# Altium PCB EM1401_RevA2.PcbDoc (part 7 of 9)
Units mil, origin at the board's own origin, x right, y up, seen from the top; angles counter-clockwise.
Board outline 7800 x 5300 mil, 6 copper layers (Top Layer, MidLayer1, MidLayer2, MidLayer3, MidLayer4, Bottom Layer), stack 16.8 mil thick; 751 components, 531 nets, 2554 pads, 1388 vias.
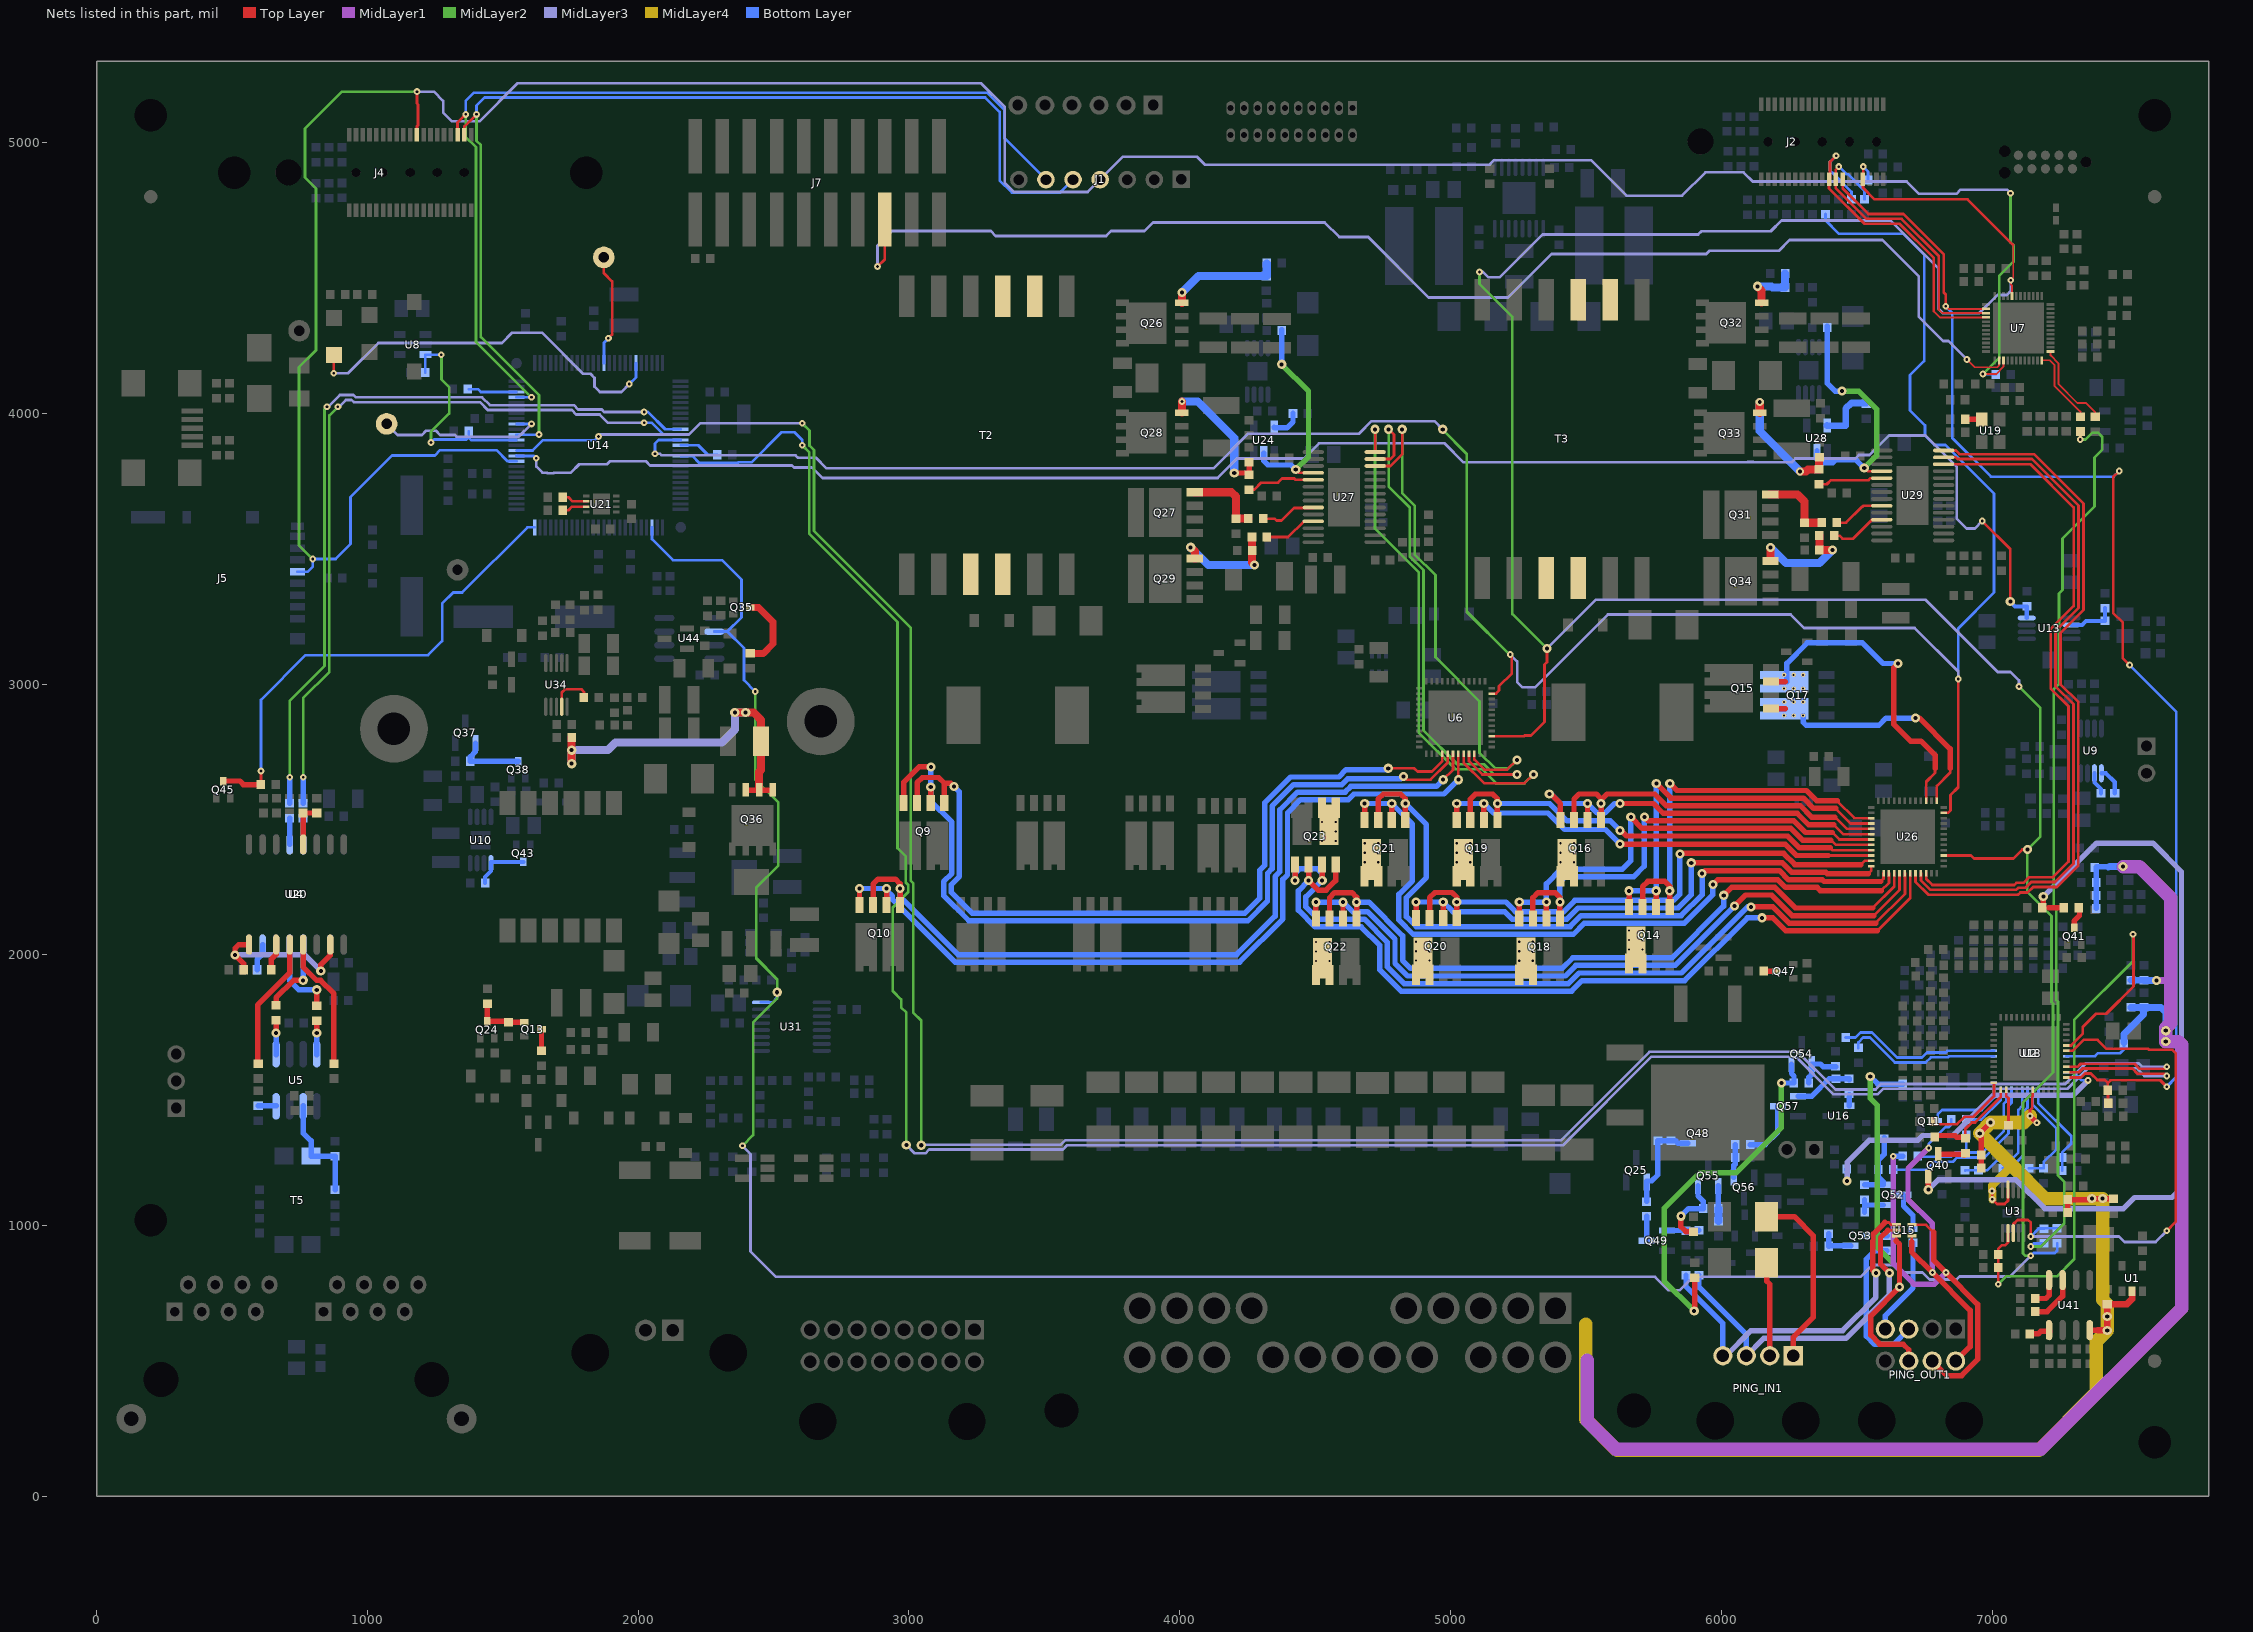
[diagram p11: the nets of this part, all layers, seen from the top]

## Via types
v1: diameter 25, hole 10, Top Layer to Bottom Layer, tented both sides, 275 vias
v2: diameter 16, hole 8, Top Layer to Bottom Layer, tented both sides, 240 vias
v3: diameter 34, hole 15, Top Layer to Bottom Layer, tented both sides, 158 vias
v4: diameter 34, hole 15, Top Layer to Bottom Layer, 154 vias
v5: diameter 34, hole 15, Top Layer to Bottom Layer, tented top, 95 vias
v6: diameter 34, hole 15, Top Layer to Bottom Layer, tented bottom, 89 vias
v7: diameter 25, hole 10, Top Layer to Bottom Layer, tented bottom, 75 vias
v8: diameter 25, hole 10, Top Layer to Bottom Layer, 62 vias
v9: diameter 28, hole 8, Top Layer to Bottom Layer, tented both sides, 60 vias
v10: diameter 24, hole 8, Top Layer to Bottom Layer, 53 vias
v11: diameter 25, hole 10, Top Layer to Bottom Layer, tented top, 28 vias
v12: diameter 50, hole 28, Top Layer to Bottom Layer, 28 vias
v13: diameter 25, hole 8, Top Layer to Bottom Layer, tented both sides, 18 vias
v14: diameter 50, hole 28, Top Layer to Bottom Layer, tented top, 12 vias
v15: diameter 25, hole 8, Top Layer to Bottom Layer, tented top, 9 vias
v16: diameter 20, hole 8, Top Layer to Bottom Layer, tented both sides, 9 vias
v17: diameter 24, hole 8, Top Layer to Bottom Layer, tented bottom, 4 vias
v18: diameter 24, hole 8, Top Layer to Bottom Layer, tented top, 4 vias
v19: diameter 28, hole 10, Top Layer to Bottom Layer, tented both sides, 3 vias
v20: diameter 35, hole 14, Top Layer to Bottom Layer, 3 vias
v21: diameter 50, hole 28, Top Layer to Bottom Layer, tented both sides, 2 vias
v22: diameter 50, hole 28, Top Layer to Bottom Layer, tented bottom, 2 vias
v23: diameter 30, hole 14, Top Layer to Bottom Layer, tented top, 2 vias
v24: diameter 28, hole 10, Top Layer to Bottom Layer, 1 vias
v25: diameter 35, hole 14, Top Layer to Bottom Layer, tented both sides, 1 vias
v26: diameter 35, hole 14, Top Layer to Bottom Layer, tented top, 1 vias

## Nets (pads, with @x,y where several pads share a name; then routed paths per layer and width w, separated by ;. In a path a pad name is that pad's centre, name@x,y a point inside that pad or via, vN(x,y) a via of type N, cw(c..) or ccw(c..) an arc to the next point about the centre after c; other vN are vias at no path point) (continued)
NetQ9_1: Q9.1 Q9.3 U6.16 | length 3029.8
  Top Layer w10: v4(4770,2689) 4866,2689 4878,2677 4931.29,2677 4969.7,2715.41 U6.16@4969.7,2742.39
  Top Layer w20: Q9.3@3030.42,2560 3030.42,2636 3049.42,2655 3109.42,2655 3130.42,2634 ; Q9.1@3130.42,2560 3130.42,2634 ; v4(3166.42,2622) 3154.42,2634 3130.42,2634
  Bottom Layer w20: v4(3166.42,2622) 3186.42,2602 3186.42,2289.5 3156.42,2259.5 3156.42,2230.5 3232.92,2154 4240.2,2154 4296,2209.8 4296,2312.63 4313.42,2330.05 4313.42,2561.22 4409.2,2657 4587.6,2657 4614.6,2684 4765,2684 v4(4770,2689)
NetQ9_2: Q9.2 Q9.4 U6.17 | length 3161.4
  Top Layer w10: v4(4826,2659) 4838,2647 4926.75,2647 4989.39,2709.64 U6.17@4989.39,2742.39
  Top Layer w20: Q9.4@2980.42,2560 2980.42,2637 3037.42,2694 v4(3081.42,2694) ; Q9.2@3080.42,2560 v4(3080.42,2620)
  Bottom Layer w20: v4(3081.42,2694) 3080.42,2693 v4(3080.42,2620) 3080.42,2568 3158.42,2490 3158.42,2301.1 3128.42,2271.1 3128.42,2218.9 3221.32,2126 4251.79,2126 4324,2198.21 4324,2301.03 4341.42,2318.45 4341.42,2549.62 4420.79,2629 4599.2,2629 4620.2,2650 4817,2650 v4(4826,2659)
NetQ10_1: Q10.1 Q10.3 U6.18 | length 2990.1
  Top Layer w10: v4(4973,2647) 5009.07,2683.07 U6.18@5009.07,2742.39
  Top Layer w20: Q10.3@2867.42,2185 2867.42,2261 2886.42,2280 2950,2280 2967.42,2262.58 v4(2967.42,2245) Q10.1@2967.42,2185
  Bottom Layer w20: v4(2967.42,2245) 2967.42,2215.57 3181.99,2001 4210,2001 4352,2143 4352,2289.43 4370,2307.43 4370,2536 4435,2601 4610.79,2601 4631.79,2622 4948,2622 v4(4973,2647)
NetQ10_2: Q10.2 Q10.4 U6.19 | length 3049.6
  Top Layer w10: v4@5028.76,2647 U6.19@5028.76,2742.39
  Top Layer w20: Q10.4@2817.42,2185 v4(2817.42,2245) ; Q10.2@2917.42,2185 v4(2917.42,2245)
  Bottom Layer w20: v4(2817.42,2245) v4(2917.42,2245) 2917.42,2238.58 2939.42,2216.58 2939.42,2203.97 3170.39,1973 4221.6,1973 4381,2132.4 4381,2278.84 4398,2295.84 4398,2524.4 4446.6,2573 4622.39,2573 4643.39,2594 4976,2594 v4(5029,2647)
NetQ11_3: Q11.3 U18.1 | length 313.3
  Bottom Layer w10: Q11.3@6799,1386 6799,1411 6815.5,1427.5 6961.5,1427.5 7006.84,1472.84 U18.1@7006.84,1527.66
NetQ13_1: Q13.1 Q24.3 R210.1 R211.1 | length 199.7
  Top Layer w20: R210.1@1443,1815 Q24.3@1443,1755 1520.01,1755 1521,1755.99 1526.4,1750.59 Q13.1@1580.01,1750.59
NetQ13_3: Q13.3 R176.1 | length 78.9
  Top Layer w20: R176.1@1643,1646.12 Q13.3@1643,1725
NetQ14_1: Q14.1 Q14.3 U26.3 | length 1462.4
  Top Layer w10: 6428,2569 6492.1,2504.9 U26.3@6554.06,2504.9
  Top Layer w20: Q14.3@5709.5,2176.58 5709.5,2252.58 5728.5,2271.58 5792.08,2271.58 5809.5,2254.17 v4(5809.5,2236.58) Q14.1@5809.5,2176.58 ; v4(5810,2633) 5836,2607 6314.77,2607 6352.77,2569 6428,2569
  Bottom Layer w20: v4(5809.5,2236.58) 5809.5,2632.5 v4(5810,2633)
NetQ14_2: Q14.2 Q14.4 U26.4 | length 1471.9
  Top Layer w10: 6422,2541 6477.79,2485.21 U26.4@6554.06,2485.21
  Top Layer w20: Q14.4@5659.5,2176.58 v4(5659.5,2236.58) ; Q14.2@5759.5,2176.58 v4(5759.5,2236.58) ; v4(5760,2633) 5814,2579 6303.17,2579 6341.17,2541 6422,2541
  Bottom Layer w20: v4(5659.5,2236.58) v4(5759.5,2236.58) 5759.5,2632.5 v4(5760,2633)
NetQ14_5: Q14.5 Q14.6 Q15.1 Q17.5 Q17.6 Q18.5 Q18.6 Q20.5 Q20.6 Q22.5 Q22.6 U26.37 | length 894
  Top Layer w10: U26.37@6796.18,2569.86 6796.18,2623.31 6845.42,2672.54 6845.42,2689
  Top Layer w20: Q15.1@6184.27,2909.24 6235.94,2909.24 ; v4(6716.79,2874.62) 6731.79,2874.62 6845.42,2761 6845.42,2689
  Bottom Layer w20: v2(6302.09,2884) 6302.09,2859.33 6313.42,2848 6581.54,2848 6608.17,2874.62 v4(6716.79,2874.62)
  other v2: 4503,1977.99 4553,1977.99 5254,1978.34 5304,1978.34 4873,1978.67 4923,1978.67 4503,2012.99 4553,2012.99 5254,2013.34 5304,2013.34 4873,2013.67 4923,2013.67 5659.5,2019.92 5709.5,2019.92 4503,2047.99 4553,2047.99 5254,2048.34 5304,2048.34 4873,2048.67 4923,2048.67 5659.5,2054.92 5709.5,2054.92 5659.5,2089.92 5709.5,2089.92 6232.09,2884 6267.09,2884 6232.09,2934 6267.09,2934 6302.09,2934
NetQ15_3: Q15.3 Q16.5 Q16.6 Q17.7 Q17.8 Q19.5 Q19.6 Q21.5 Q21.6 Q23.5 Q23.6 U26.39 | length 1203.8
  Top Layer w10: U26.39@6756.81,2569.86 6756.81,2639.4 6789.42,2672 6789.42,2689
  Top Layer w20: Q15.3@6184.27,3009.24 6235.94,3009.24 ; v6(6652.42,3076) 6637.42,3061 6637.42,2851 6698.92,2789.5 6737.51,2789.5 6789.42,2737.6 6789.42,2689
  Bottom Layer w20: Q17.8@6242.09,3009 6242.09,3076.68 6317.42,3152 6521.42,3152 6597.42,3076 v6(6652.42,3076)
  other v2: 4683,2342.34 4733,2342.34 5023,2342.34 5073,2342.34 5406,2342.34 5456,2342.34 4683,2377.34 4733,2377.34 5023,2377.34 5073,2377.34 5406,2377.34 5456,2377.34 4683,2412.34 4733,2412.34 5023,2412.34 5073,2412.34 5406,2412.34 5456,2412.34 4526,2421 4576,2421 4526,2456 4576,2456 4526,2491 4576,2491 6232.09,2984 6267.09,2984 6302.09,2984 6232.09,3034 6267.09,3034 6302.09,3034
NetQ16_1: Q16.1 Q16.3 U26.5 | length 1329.1
  Top Layer w10: 6420,2509 6463.47,2465.53 U26.5@6554.06,2465.53
  Top Layer w20: Q16.3@5456,2499 5456,2575 5475,2594 5538.58,2594 5556,2576.58 v4@5556,2572 ; Q16.1@5556,2499 v4(5556,2559) v4@5556,2572 ; 6420,2509 6333.58,2509 6291.58,2551 5796.6,2551 5753.6,2594 5578,2594 v4@5556,2572
NetQ16_2: Q16.2 Q16.4 U26.6 | length 1454.9
  Top Layer w10: 6416,2480 6450.16,2445.84 U26.6@6554.06,2445.84
  Top Layer w20: v4(5365,2594) 5371,2594 5406,2559 Q16.4@5406,2499 ; Q16.2@5506,2499 v4(5506,2559) ; v4(5626,2559) 5749,2559 5785,2523 6279.98,2523 6322.98,2480 6416,2480
  Bottom Layer w20: v4(5365,2594) 5371,2594 5406,2559 v4(5506,2559) 5506.5,2559 5541.5,2524 5570.5,2524 5605.5,2559 v4(5626,2559)
NetQ18_1: Q18.1 Q18.3 U26.7 | length 1733.4
  Top Layer w10: 6410,2452 6435.84,2426.16 U26.7@6554.06,2426.16
  Top Layer w20: Q18.3@5304,2135 5304,2211 5323,2230 5386.58,2230 5404,2212.58 v4(5404,2195) Q18.1@5404,2135 ; v4(5716,2509) 5730,2495 6268.38,2495 6311.38,2452 6410,2452
  Bottom Layer w20: v4(5404,2195) 5404,2270 5422.34,2288.34 5676.34,2288.34 5715.5,2327.5 5715.5,2509 v4(5716,2509)
NetQ18_2: Q18.2 Q18.4 U26.8 | length 1726.1
  Top Layer w10: 6405,2424 6405.53,2424 6423.05,2406.47 U26.8@6554.06,2406.47
  Top Layer w20: Q18.4@5254,2135 v4(5254,2195) ; Q18.2@5354,2135 v4(5354,2195) ; v4(5666,2509) 5708,2467 6256.78,2467 6299.78,2424 6405,2424
  Bottom Layer w20: v4(5254,2195) v4(5354,2195) 5354,2262 5408.34,2316.34 5634.34,2316.34 5666,2348 v4(5666,2509)
NetQ19_1: Q19.1 Q19.3 U26.9 | length 1718.5
  Top Layer w10: 6401.9,2395.1 6410.21,2386.79 U26.9@6554.06,2386.79
  Top Layer w20: Q19.3@5073,2499 5073,2575 5092,2594 5155.58,2594 5173,2576.58 v4(5173,2559) Q19.1@5173,2499 ; v4@5629,2460 5650,2439 6245.19,2439 6289.08,2395.1 6401.9,2395.1
  Bottom Layer w20: v4(5173,2559) 5366.4,2559 5430.4,2495 5590,2495 v4(5626,2459)
NetQ19_2: Q19.2 Q19.4 U26.10 | length 1730.5
  Top Layer w10: 6396,2367.1 U26.10@6554.06,2367.1
  Top Layer w20: Q19.4@5023,2499 v4(5023,2559) ; Q19.2@5123,2499 v4(5123,2559) ; v4@5626,2407.1 5626.9,2408 6236.59,2408 6277.48,2367.1 6396,2367.1
  Bottom Layer w20: v4(5023,2559) v4(5123,2559) 5123.5,2559 5158.5,2524 5360,2524 5421,2463 5572,2463 v4(5626,2409)
NetQ20_1: Q20.1 Q20.3 U26.11 | length 2013.7
  Top Layer w10: 6515,2333 6529.42,2347.42 U26.11@6554.06,2347.42
  Top Layer w20: Q20.3@4923,2135.33 4923,2211.33 4942,2230.33 5005.58,2230.33 5023,2212.91 v4(5023,2195.33) Q20.1@5023,2135.33 ; v4(5847,2373) 5849,2375 6229.99,2375 6271.99,2333 6515,2333
  Bottom Layer w20: v4(5023,2195.33) 5204.17,2195.33 5239.5,2160 5418.5,2160 5459.5,2201 5823.41,2201 5847,2224.59 v4(5847,2373)
NetQ20_2: Q20.2 Q20.4 U26.12 | length 2020
  Top Layer w10: 6542,2300 6554.06,2312.06 U26.12@6554.06,2327.73
  Top Layer w20: Q20.4@4873,2135.33 v4(4873,2195.33) ; Q20.2@4973,2135.33 v4(4973,2195.33) ; v4(5889,2340) 6225.39,2340 6260.39,2305 6386.1,2305 6391.1,2300 6542,2300
  Bottom Layer w20: v4(4873,2195.33) v4(4973,2195.33) 5008.33,2160 5199.9,2160 5227.9,2132 5430.1,2132 5471.1,2173 5840.4,2173 5889,2221.6 v4(5889,2340)
NetQ21_1: Q21.1 Q21.3 U26.14 | length 2700.4
  Top Layer w10: 6589,2271 6599.33,2281.33 U26.14@6599.33,2302.14
  Top Layer w20: Q21.3@4733,2499 4733,2575 4752,2594 4815.58,2594 4833,2576.58 v4(4833,2559) Q21.1@4833,2499 ; v4(5929,2300) 5940,2311 6214.79,2311 6248.79,2277 6373.89,2277 6379.89,2271 6589,2271
  Bottom Layer w20: v4(4833,2559) 4911,2481 4911,2286 4837,2212 4837,2141 4874,2104 5441.69,2104 5482.69,2145 5852,2145 5929,2222 v4(5929,2300)
NetQ21_2: Q21.2 Q21.4 U26.15 | length 2703.9
  Top Layer w10: 6590,2237 6619.02,2266.02 U26.15@6619.02,2302.14
  Top Layer w20: Q21.4@4683,2499 v4(4683,2559) ; Q21.2@4783,2499 v4(4783,2559) ; v4(5969,2260) 5986,2277 6209.2,2277 6237.2,2249 6353.81,2249 6365.81,2237 6590,2237
  Bottom Layer w20: v4(4683,2559) v4(4783,2559) 4859,2483 4859,2273.6 4809,2223.6 4809,2129.4 4862.4,2076 5453.29,2076 5494.29,2117 5863.6,2117 5969,2222.4 v4(5969,2260)
NetQ22_1: Q22.1 Q22.3 U26.16 | length 2669.6
  Top Layer w10: 6559,2173 6638.7,2252.7 U26.16@6638.7,2302.14
  Top Layer w20: Q22.3@4553,2134.65 4553,2210.65 4572,2229.65 4635.59,2229.65 4653,2212.24 v4(4653,2194.65) Q22.1@4653,2134.65 ; v4(6009,2220) 6038,2249 6197.5,2249 6273.5,2173 6559,2173
  Bottom Layer w20: v4(4653,2194.65) 4698.35,2194.65 4823,2070 4823,1980 4853,1950 5412.43,1950 5451.43,1989 5818,1989 6009,2180 v4(6009,2220)
NetQ22_2: Q22.2 Q22.4 U26.17 | length 2698
  Top Layer w10: 6564,2145 6658.39,2239.39 U26.17@6658.39,2302.14
  Top Layer w20: Q22.4@4503,2134.65 v4(4503,2194.65) ; Q22.2@4603,2134.65 v4(4603,2194.65) ; v4(6049,2180) 6090,2221 6185.9,2221 6261.9,2145 6564,2145
  Bottom Layer w20: v4(4503,2194.65) v4(4603,2194.65) 4603.51,2194.65 4638.51,2159.65 4693.35,2159.65 4795,2058 4795,1968.4 4841.4,1922 5424.03,1922 5463.03,1961 5829.6,1961 6048.6,2180 v4(6049,2180)
NetQ23_1: Q23.1 Q23.3 U26.18 | length 3055.2
  Top Layer w10: 6570,2117 6678.07,2225.07 U26.18@6678.07,2302.14
  Top Layer w20: v4(4426,2274.34) Q23.1@4426,2334.34 ; v4(4526,2274.34) Q23.3@4526,2334.34 ; v4(6110,2177) 6190.31,2177 6250.31,2117 6570,2117
  Bottom Layer w20: v4(4426,2274.34) 4426,2301 4443,2318 4508,2318 4526,2300 v4(4526,2274.34) 4466,2214.34 4466,2177 4511.35,2131.65 4681.75,2131.65 4767,2046.4 4767,1956 4829,1894 5435.63,1894 5474.63,1933 5853,1933 6097,2177 v4(6110,2177)
NetQ23_2: Q23.2 Q23.4 U26.19 | length 3085.5
  Top Layer w10: 6577,2089 6697.76,2209.76 U26.19@6697.76,2302.14
  Top Layer w20: Q23.2@4476,2334.34 v4(4476,2274.34) 4511.34,2239 4540.66,2239 4576,2274.34 Q23.4@4576,2334.34 ; v4(6150,2137) 6190.71,2137 6238.71,2089 6577,2089
  Bottom Layer w20: v4(4476,2274.34) 4438,2236.34 4438,2165.4 4499.75,2103.65 4670.15,2103.65 4739,2034.8 4739,1944.4 4817,1866.4 4817,1866 5447.22,1866 5486.22,1905 5864.6,1905 6096.6,2137 v4(6150,2137)
NetQ25_1: Q25.1 Q48.1 R89.1 R183.1 R186.1 | length 368.4
  Bottom Layer w20: R186.1@5724,1089.12 Q25.1@5724,1161.06 5724,1165 5743,1165 5766,1188 R89.1@5766,1313.88 R183.1@5814,1313.88 5830.12,1313.88 5840,1304 Q48.1@5877,1304
NetQ26_4: Q26.4 R171.1 R172.1 | length 422.6
  Top Layer w30: Q26.4@4008.42,4408 v5(4008.42,4446)
  Bottom Layer w30: v5(4008.42,4446) 4069.53,4507.12 R171.1@4319.42,4507.12 4321.42,4507.12 R172.1@4321.42,4553.44
NetQ27_4: Q27.4 R170.1 R173.2 | length 281.5
  Top Layer w30: Q27.4@4055.78,3708.53 4191.88,3708.53 4207.42,3693 R173.2@4207.42,3611 ; R173.2@4212.42,3611 R170.1@4253.86,3611
NetQ28_4: Q28.4 R175.1 R177.2 | length 513.9
  Top Layer w20: v5(4201.42,3780) 4201.86,3779.56 4256.42,3779.56 R177.2@4256.42,3819
  Top Layer w30: Q28.4@4008,4003 4008,4043.92 v11(4008.08,4044)
  Bottom Layer w30: v11(4008.08,4044) 4066.42,4044 4201.42,3909 v5(4201.42,3780)
NetQ29_4: Q29.4 R178.2 R180.1 | length 417.5
  Top Layer w30: v3(4040.42,3505) 4055.78,3489.63 Q29.4@4055.78,3464.53 ; R178.2@4267.48,3543 R180.1@4267.48,3493 4267.48,3448.94 v5(4276.42,3440)
  Bottom Layer w30: v3@4040.42,3506 v3(4040.42,3505) 4105.42,3440 v5(4276.42,3440)
NetQ31_4: Q31.4 R188.1 R191.2 | length 270.3
  Top Layer w30: Q31.4@6180.5,3700.5 6280.92,3700.5 6307.42,3674 R191.2@6307.42,3596 ; R191.2@6316.42,3596 R188.1@6370.86,3596
NetQ32_4: Q32.4 R189.1 R190.1 | length 220.2
  Top Layer w30: v3(6134,4469) 6148.92,4454.08 Q32.4@6148.92,4409
  Bottom Layer w30: v3(6134,4469) 6185,4469 6189,4465 R189.1@6235.3,4465 6235.42,4465.12 R190.1@6235.42,4516
NetQ33_4: Q33.4 R194.1 R195.2 | length 477.2
  Top Layer w30: Q33.4@6142,4002 v23(6142,4042) ; v23(6290.98,3785.56) 6312.98,3785.56 6320.42,3793 6360.98,3793 R194.1@6361.42,3792.56 6361.42,3836.44 R195.2@6362.42,3837.44
  Bottom Layer w30: v23(6142,4042) 6142,3934.53 v23(6290.98,3785.56)
NetQ34_4: Q34.4 R196.2 R198.1 | length 423.7
  Top Layer w30: Q34.4@6181.58,3455 v3(6181.58,3504) v3@6181.58,3505 ; R196.2@6362.3,3548.12 6362.53,3547.88 R198.1@6362.53,3495 6362.65,3494.88 v5(6410.53,3494.88)
  Bottom Layer w30: v3(6181.58,3504) 6238.58,3447 6362.65,3447 v5(6410.53,3494.88)
NetQ35_3: Q35.3 R148.1 | length 286.3
  Top Layer w25: Q35.3@2413.5,3283 2445,3283 2498,3230 2498,3148.97 2462.15,3113.12 R148.1@2414,3113.12
NetQ36_1: Q36.1 Q36.2 Q36.3 R221.2 R224.2 | length 1354.6
  Top Layer w20: Q36.3@2396.92,2608.66 2446.92,2608.66 Q36.1@2496.92,2608.66
  Top Layer w30: R221.2@1754.06,2803 1754.06,2756.44 v3(1754.5,2756) v3(1754.5,2706) ; v5(2357,2895) v5(2397,2895) 2427,2895 2454,2868 R224.2@2454,2789 2454,2683 2446.92,2675.92 Q36.2@2446.92,2609.89 Q36.2@2446.92,2608.66
  MidLayer3 w30: v3(1754.5,2706) v3(1754.5,2756) 1888.07,2756 1916.07,2784 2309,2784 2357,2832 v5(2357,2895) v5(2397,2895)
NetQ37_1: Q37.1 Q38.3 R44.2 | length 252.5
  Bottom Layer w20: Q37.1@1399.4,2782.6 1399.4,2750.4 1380.12,2731.12 R44.2@1380.12,2715 Q38.3@1557,2715
NetQ40_1: Q40.1 R126.1 R127.2 | length 2968.8
  Top Layer w20: Q40.1@6764.01,1181.32 6764.01,1133.4 v3(6764.42,1133) v3@6764.42,1131 ; v3(7189.3,2215.88) 7189.42,2215.77 R126.1@7189.42,2173.99 ; 7209.42,2174 R127.2@7256.42,2174
  MidLayer3 w20: v3(6764.42,1133) 6800.92,1169.5 7088.5,1169.5 7195,1063 7485.42,1063 7526.42,1104 7664.42,1104 7699.42,1139 7699.42,2307 7593.42,2413 7386.42,2413 v3(7189.3,2215.88)
NetQ40_3: Q40.3 R35.2 | length 102.5
  Top Layer w20: Q40.3@6801.42,1264 6802.42,1263 6896.42,1263 R35.2@6897.42,1264 ; R35.2@6897.42,1260 R35.2@6901.42,1264
NetQ41_3: Q41.3 R127.1 | length 83.1
  Top Layer w20: Q41.3@7303.42,2099 Q41.3@7303.42,2100 7303.42,2125 7323,2144.58 R127.1@7323,2174
NetQ43_3: Q43.3 R93.2 U10.5 | length 205.8
  Bottom Layer w15: R93.2@1435.12,2266 1435.12,2288.12 1456.39,2309.39 U10.5@1456.39,2338.37 1456.39,2343.34 1575.83,2343.34 Q43.3@1576,2343.5
NetQ45_3: Q45.3 R67.2 U14.50 | length 1813.4
  Top Layer w10: R67.2@607,2629 v11(607,2679)
  Top Layer w20: Q45.3@467.41,2641.99 529.01,2641.99 542,2629 R67.2@607,2629
  Bottom Layer w10: v11(607,2679) 607,2942 772,3107 1224,3107 1276,3159 1276,3297 1317,3338 1350,3338 1590.85,3578.85 U14.50@1617.78,3578.85
NetQ47_3: Q47.3 R168.2 | length 46.9
  Top Layer w20: R168.2@6155.98,1940 Q47.3@6202.92,1940
NetQ49_1: Q49.1 R184.2 R185.1 | length 118.7
  Bottom Layer w20: Q49.1@5799,982 R185.1@5869.56,982 5870.44,982 5871,982.56 5871.56,982 5872.12,982.56 R184.2@5917,982.56
NetQ49_3: Q49.3 R186.2 | length 89.8
  Bottom Layer w20: Q49.3@5724,944.8 Q49.3@5724.2,944.6 5724.2,1033.8 R186.2@5724,1034
NetQ52_1: Q52.1 R260.1 R261.2 | length 115.5
  Bottom Layer w20: R260.1@6529,1050 6529,1076 ; R261.2@6529,1096.44 6529,1076 ; Q52.1@6598,1076.2 6529.2,1076.2 6529,1076
NetQ52_3: Q52.3 R259.1 | length 136.6
  Bottom Layer w20: Q52.3@6672.8,1113.6 6672.8,1073.2 6708,1038 R259.1@6708,991.56
NetQ53_1: Q53.1 R263.2 R264.1 | length 128.9
  Bottom Layer w20: R263.2@6396,970.44 6396.12,970.32 R264.1@6396.12,924 6397.31,925.2 Q53.1@6478,925.2
NetQ53_3: Q53.3 R262.1 | length 60.4
  Bottom Layer w20: Q53.3@6552.8,962.6 6553.28,962.12 R262.1@6613,962.12
NetQ54_1: Q54.1 R265.2 R266.1 | length 166.5
  Bottom Layer w20: R265.2@6323.56,1527 6323.56,1547.56 6334,1558 Q54.1@6334,1597 6366,1597 6376,1587 R266.1@6422,1587
NetQ54_2: Q54.2 R59.2 R265.1 | length 1382.1
  Top Layer w20: v4@5902,685 R59.2@5902,807.94
  MidLayer2 w20: v4@5894.84,689.59 5790,794.44 5790,1065 5920,1195 6055,1195 6222,1362 v6(6222,1527)
  Bottom Layer w20: v6(6222,1527) R265.1@6268.44,1527 6268.44,1552.56 6259.2,1561.8 Q54.2@6259.2,1597
  other v4: 5900,685
NetQ55_1: Q55.1 R269.2 R270.1 | length 129.9
  Bottom Layer w20: Q55.1@5988.8,1147 5988.8,1063.32 R269.2@5989.12,1063
  Bottom Layer w30: R269.2@5989.12,1063 5990,1062.12 R270.1@5990,1017.56
NetQ55_2: Q55.2 R60.2 R269.1 | length 280.4
  Top Layer w20: v3(5851,1035) 5851,996 5869.12,977.88 R60.2@5898,977.88
  Bottom Layer w20: v3(5851,1035) 5879,1063 R269.1@5934,1063 5934,1090 5914,1110 Q55.2@5914,1147
NetQ56_1: Q56.1 R272.2 R273.1 | length 122.8
  Bottom Layer w20: Q56.1@6046.6,1178.4 6046.6,1222.6 6051.44,1227.44 R273.1@6051.44,1251 6051,1251.44 R272.2@6051,1299
NetQ57_1: Q57.1 R274.2 R276.1 | length 214.9
  Bottom Layer w20: Q57.1@6283.8,1478.4 6334.4,1478.4 6398.56,1542.56 R274.2@6424,1542.56 R276.1@6472,1542.56 ; R276.1@6471.88,1538 R276.1@6472,1538.12
NetQ57_3: Q57.3 R272.1 | length 217.3
  Bottom Layer w20: R272.1@6106.12,1299 6162,1299 6209,1346 Q57.3@6209,1441
NetR17_2: R17.2 R35.1 U2.25 | length 344.2
  Top Layer w10: R35.1@6900.42,1329.94 6900.42,1356 6925.42,1381 6937.42,1381 7032.43,1476.01 U2.25@7032.43,1502.07
  Top Layer w20: R17.2@6792.41,1326.65 6798.75,1333 6863.5,1333 6869.84,1326.65 6897.08,1326.65 R35.1@6897.42,1326.99
NetR18_2: R18.2 U2.24 | length 310.6
  Top Layer w10: R18.2@6788.47,1374.65 6871.07,1374.65 6898.42,1402 6930.42,1402 7006.84,1478.42 U2.24@7006.84,1527.66
NetR19_2: R19.2 U2.26 | length 135.5
  Top Layer w10: U2.26@7052.11,1502.07 7052.11,1479.31 7060.91,1470.5 R19.2@7060.91,1370.21
NetR25_1: R25.1 U4.4 | length 287.4
  Top Layer w20: R25.1@663,1813.12 663,1842 727,1906 v6(763,1906)
  Bottom Layer w20: v6(763,1906) U4.4@763,2037.96
NetR25_2: R25.2 U5.1 | length 126.5
  Top Layer w20: v3(663,1712) R25.2@663,1758
  Bottom Layer w20: U5.1@663,1631.49 U5.1@663,1633.46 v3(663,1712)
NetR26_2: R26.2 R40.1 T5.4 U5.6 | length 410.4
  Bottom Layer w20: U5.6@763,1442.51 U5.6@763,1440.54 763,1342 792,1313 T5.4@792,1257 R26.2@881,1257 R40.1@881,1133.12
NetR27_1: R27.1 U14.11 | length 2846.2
  MidLayer2 w10: v1(763,2656) 763,2948.4 859.5,3044.9 859.5,3992.5 v8(891,4024)
  MidLayer3 w10: v8(891,4024) 894.94,4024 920.44,4049.5 941.56,4049.5 950.06,4041 1415.57,4041 1444.57,4012 1755.02,4012 1771.02,3996 1858,3996 1889,3965 v7(2022,3965)
  Bottom Layer w10: v7(2022,3965) 2050.5,3965 2094.13,3921.37 U14.11@2157.15,3921.37
  Bottom Layer w20: R27.1@763,2560.56 v1(763,2656)
NetR27_2: R27.2 U4.13 | length 97.4
  Bottom Layer w20: U4.13@763,2408.04 R27.2@763,2505.44
NetR28_1: R28.1 U4.5 | length 305.5
  Top Layer w20: R28.1@813,1812.56 v6(813,1871)
  Bottom Layer w20: U4.5@713,2037.96 713,1905 747,1871 v6(813,1871)
NetR28_2: R28.2 U5.4 | length 126
  Top Layer w20: v3(813,1712) R28.2@813,1757.44
  Bottom Layer w20: U5.4@813,1631.49 U5.4@813,1633.46 v3(813,1712)
NetR31_1: R31.1 U41.1 | length 76.4
  Top Layer w20: R31.1@7139.97,600.65 7170.65,600.65 7179.65,609.65 7211.93,609.65 U41.1@7212.41,610.14
NetR32_1: R32.1 U41.8 | length 101.6
  Top Layer w20: R32.1@7169.98,731 7198.42,731 7210.41,743 U41.8@7210.41,799.17
NetR33_1: R33.1 U41.7 | length 173.4
  Top Layer w20: R33.1@7169.97,682.65 7203.07,682.65 7260.41,740 U41.7@7260.41,799.17
NetR38_1: R38.1 U14.10 | length 2897.1
  MidLayer2 w10: v1(713,2656) 713,2938 841.5,3066.5 841.5,4014.5 v8(851,4024)
  MidLayer3 w10: v8(851,4024) 854.94,4024 898.44,4067.5 949.02,4067.5 957.52,4059 1423.02,4059 1452.02,4030 1762.47,4030 1778.47,4014 1865.46,4014 1874.46,4005 v7(2022,4005)
  Bottom Layer w10: v7(2022,4005) 2036,4005 2099.94,3941.06 U14.10@2157.15,3941.06
  Bottom Layer w20: R38.1@713,2560.56 v1(713,2656)
NetR38_2: R38.2 U4.12 | length 97.4
  Bottom Layer w20: U4.12@713,2408.04 R38.2@713,2505.44
NetR56_2: R56.2 U14.13 | length 149.3
  Bottom Layer w10: U14.13@2157.15,3882 2222,3882 2257,3847 R56.2@2292,3847
NetR61_1: R61.1 U14.73 | length 181.1
  Bottom Layer w10: R61.1@1374,4089 1409,4089 1419,4079 1550.7,4079 U14.73@1550.85,4078.85
NetR62_1: R62.1 U4.7 | length 101.2
  Bottom Layer w20: R62.1@593,1945 593,1983 613,2003 U4.7@613,2037.96
NetR66_1: R66.1 U5.8 | length 66
  Bottom Layer w20: R66.1@597,1442.56 662.95,1442.56 U5.8@663,1442.51
NetR76_1: R76.1 U7.13 | length 331.5
  Top Layer w7: U7.13@7216.09,4228.39 7216.09,4213.91 7245,4185 7245,4108.49 7315.49,4038 7347,4038 7381,4004 R76.1@7381,3987.56 R76.1@7381,3983.62
NetR80_1: R80.1 U7.12 | length 288
  Top Layer w7: U7.12@7183.61,4195.91 7212.88,4195.91 7230,4178.79 7230,4102.27 7326,4006.27 R80.1@7326,3987.94 R80.1@7326,3984
NetR86_1: R86.1 U19.3 | length 62.1
  Top Layer w20: R86.1@6900.56,3978 6962,3978 U19.3@6962.5,3977.5
NetR88_2: R88.2 U21.7 | length 92.3
  Top Layer w10: R88.2@1722,3642 1743,3642 1756.16,3655.16 U21.7@1808.88,3655.16
NetR94_2: R94.2 U13.4 U14.61 | length 6346.6
  Top Layer w10: v11(6963.42,3602) 7067.42,3498 v6(7067.42,3305)
  MidLayer3 w10: v7(1624,3834) 1624,3803 1646,3781 1662.94,3781 1665.44,3778.5 1686.56,3778.5 1689.06,3781 1751.46,3781 1782.46,3812 1884.46,3812 1895.46,3823 2028.48,3823 2043.98,3807.5 2568.07,3807.5 2575.57,3800 2641.63,3800 2680.63,3761 4139.99,3761 4211.99,3833 4458.3,3833 4514.3,3889 4978.75,3889 5048.75,3819 6095.94,3819 6097.44,3820.5 6118.56,3820.5 6120.06,3819 6259.36,3819 6273.36,3833 6494.81,3833 6507.96,3846.15 6547.69,3846.15 6619.54,3918 6754.46,3918 6869.42,3803.04 6869.42,3611 6905.42,3575 6936.42,3575 v11(6963.42,3602)
  Bottom Layer w10: U14.61@1549.54,3843.94 U14.61@1550.85,3842.63 1615.37,3842.63 v7(1624,3834)
  Bottom Layer w15: v6(7067.42,3305) 7085.41,3287.01 R94.2@7129.64,3287.01 7128.01,3285.38 U13.4@7128.01,3244.15
NetR95_1: R95.1 U20.3 | length 100.2
  Top Layer w20: R95.1@645.56,1945 645.56,1984.56 663,2002 U20.3@663,2037.96
NetR96_1: R96.1 R98.1 U13.6 | length 176.8
  Bottom Layer w15: U13.6@7293.36,3218.56 7332.97,3218.56 7347.54,3233.12 R96.1@7416.64,3233.12 R98.1@7416.64,3280.57
NetR115_2: R115.2 R199.1 U18.44 | length 461.3
  Bottom Layer w10: R115.2@6900.42,1204 6900.53,1204.12 R199.1@6949.42,1204.12 6981.67,1204.12 7018.3,1240.75 7062.2,1240.75 7062.46,1241 7067,1241 7096.92,1270.92 7096.92,1427.22 7111.17,1441.47 U18.44@7111.17,1502.07
NetR117_2: R117.2 R255.1 U18.43 | length 355.6
  Bottom Layer w10: R255.1@7040.42,1212 R117.2@7088.42,1212 7088.42,1232.42 7114.92,1258.92 7114.92,1419.77 7130.85,1435.7 U18.43@7130.85,1502.07
NetR119_2: R119.2 R256.1 U18.42 | length 399.6
  Bottom Layer w10: R119.2@7136.42,1212.12 7190.3,1212.12 R256.1@7190.42,1212 7190.42,1234.42 7237.42,1281.42 7237.42,1359 7150.54,1445.88 U18.42@7150.54,1502.07
NetR121_2: R121.2 R257.1 U18.41 | length 363.7
  Bottom Layer w10: U18.41@7170.22,1502.07 7170.22,1453.2 7292.42,1331 7292.42,1304 7259,1270.58 R121.2@7259,1251 7259,1203.42 R257.1@7259.42,1203
NetR159_2: R159.2 R165.2 U20.12 | length 166
  Top Layer w20: U20.12@763,2408.04 R159.2@763,2524 R165.2@813,2524
NetR160_1: R160.1 U20.4 | length 488.3
  Top Layer w20: R160.1@595,1598.56 595,1815 713,1933 U20.4@713,2037.96
NetR161_1: R161.1 U18.46 | length 647.5
  Bottom Layer w10: R161.1@6634.53,1207 6757.89,1207 6786.89,1236 6854.88,1236 6870.88,1252 6972,1252 7060.92,1340.92 7060.92,1442.13 7071.8,1453.01 U18.46@7071.8,1502.07
NetR162_1: R162.1 U18.34 | length 1221.4
  MidLayer3 w20: v3(6464.42,1165) 6464.42,1233.42 6547,1316 6726.29,1316 6743.29,1333 6855.13,1333 7003.63,1481.5 7298.92,1481.5 7353.97,1536.55 v1@7354.42,1537
  Bottom Layer w10: U18.34@7274.55,1567.03 7299.85,1567.03 7329.87,1537 7354.42,1537 v1@7353.97,1536.55
  Bottom Layer w20: R162.1@6463.86,1209 6464.42,1208.44 v3(6464.42,1165)
  other v1: 7353.94,1536.55
NetR163_1: R163.1 U20.5 | length 494.7
  Top Layer w20: U20.5@763,2037.96 763,1956 813,1906 827.5,1906 876,1857.5 R163.1@876,1598.56
NetR164_2: R164.2 U20.1 U20.7 | length 602.9
  Top Layer w20: R164.2@543,1945 543,1968 v6(511,2000) 511,2024 524.96,2037.96 U20.1@563,2037.96 ; v6(828,1941) 828,1964 863,1999 U20.7@863,2037.96
  MidLayer3 w20: v6(511,2000) 769,2000 v6(828,1941)
NetR170_2: R170.2 U27.23 | length 207.1
  Top Layer w10: R170.2@4308.98,3611 4350.42,3611 4357.42,3604 4375.99,3604 4421.99,3650 4491.13,3650 U27.23@4493.28,3652.15
NetR175_2: R175.2 U27.19 | length 255.5
  Top Layer w10: R175.2@4256.42,3718.44 4275.43,3718.44 4300.99,3744 4363.42,3744 4378.42,3759 4423.42,3759 4427.91,3754.51 U27.19@4493.28,3754.51
NetR178_1: R178.1 U27.25 | length 195.3
  Top Layer w10: R178.1@4321.98,3543 4400.3,3543 4458.26,3600.97 U27.25@4493.28,3600.97
NetR181_1: R181.1 U18.6 | length 578
  Bottom Layer w10: R181.1@6506,1655 R181.1@6506,1657 6506,1677 6524,1695 6549,1695 6641.08,1602.92 6754.92,1602.92 6773.79,1621.79 6837.2,1621.79 6841.5,1626.08 U18.6@7006.84,1626.08
NetR182_2: R182.2 U18.7 | length 603.8
  Bottom Layer w10: R182.2@6458.98,1695 6496,1695 6514.11,1713.11 6552.35,1713.11 6552.46,1713 6556.46,1713 6648.53,1620.92 6705.88,1620.92 6705.96,1621 6741.42,1621 6760.2,1639.79 6829.75,1639.79 6835.73,1645.77 U18.7@7006.84,1645.77
NetR188_2: R188.2 U29.23 | length 192.5
  Top Layer w10: R188.2@6425.98,3596 6461.27,3596 6520.3,3655.03 6520.88,3655.03 6524.14,3658.29 U29.23@6592.7,3658.29
NetR194_2: R194.2 U29.19 | length 228.1
  Top Layer w10: R194.2@6373.98,3738 6389.42,3738 6404.42,3753 6543.42,3753 6551.07,3760.66 U29.19@6592.7,3760.66
NetR196_1: R196.1 U29.25 | length 208.9
  Top Layer w10: R196.1@6417.42,3548.12 6436.3,3548.12 6447.42,3537 6487.42,3537 6557.53,3607.11 U29.25@6592.7,3607.11
NetR222_2: R222.2 U34.9 | length 164.5
  Top Layer w10: U34.9@1717.89,2916.32 1717.89,2968.39 1730.5,2981 1790,2981 1799.88,2971.12 R222.2@1799.88,2950
NetR241_1: R241.1 U9.5 | length 104.5
  Bottom Layer w15: U9.5@7403.59,2670.65 7421.35,2670.65 7453,2639 R241.1@7453,2597
NetR242_1: R242.1 U9.6 | length 84
  Bottom Layer w15: U9.6@7378,2670.65 7378,2637 7403,2612 R242.1@7403,2597
NetR275_1: R275.1 U24.5 | length 111.9
  Bottom Layer w20: U24.5@4348.22,3948 4350.22,3946 4396,3946 4418.35,3968.35 R275.1@4418.35,4000
NetR276_2: R276.2 U16.1 | length 40.8
  Bottom Layer w20: R276.2@6472,1483 6472.37,1482.63 U16.1@6472.37,1442.4
NetR277_1: R277.1 U28.5 | length 217.1
  Bottom Layer w25: U28.5@6390.82,3955.49 6392.31,3954 6459.42,3954 6459.42,4017 6480.91,4038.5 R277.1@6535.42,4038.5
NetR286_2: R286.2 U21.6 | length 93.2
  Top Layer w10: R286.2@1722,3690 1743,3690 1758.16,3674.84 U21.6@1808.88,3674.84
NetT2_2: T2.2 T2.3
NetT2_9: T2.9 T2.10
NetT3_2: T3.2 T3.3
NetT3_9: T3.9 T3.10
NetTP2_1: TP2.1 U14.67 | length 642.1
  MidLayer3 w10: TP2.1@1071,3961 1112,3920 1201.48,3920 1216.98,3935.5 1253.02,3935.5 1268.52,3920 1323.06,3920 1329.14,3913.93 1558.93,3913.93 v7(1606,3961)
  Bottom Layer w10: U14.67@1550.85,3960.74 1605.74,3960.74 v7(1606,3961)
NetU6_20: U6.20 U27.14 | length 2120.1
  Top Layer w10: v5(4721.42,3941) 4721.62,3940.79 U27.14@4721.62,3856.87 ; U6.20@5048.44,2742.39 5048.44,2709.64 5124.09,2634 5274,2634 v4(5306,2666)
  MidLayer2 w10: v5(4721.42,3941) 4721.42,3574.21 4882.42,3413.21 4882.42,2821 5017.42,2686 5115.54,2686 5167.54,2634 5274,2634 v4(5306,2666)
NetU6_21: U6.21 U27.13 | length 1982.5
  Top Layer w10: U27.13@4721.62,3831.28 4778.7,3831.28 4791.42,3844 4791.42,3921 v5(4771.42,3941) ; U6.21@5068.13,2742.39 5068.13,2715.41 5117.54,2666 v4(5245,2666)
  MidLayer2 w10: v5(4771.42,3941) 4771.42,3729.63 4849.42,3651.63 4849.42,3471.66 4900.42,3420.66 4900.42,2828.46 5024.87,2704 5123,2704 5161,2666 v4(5245,2666)
NetU6_22: U6.22 U27.12 | length 1907.9
  Top Layer w10: U27.12@4721.62,3805.69 4778.56,3805.69 4821.42,3848.54 v5(4821.42,3941) ; U6.22@5087.81,2742.39 5087.81,2721.18 5125,2684 5209.42,2684 v4(5245.42,2720)
  MidLayer2 w10: v5(4821.42,3941) 4821.42,3705.09 4867.42,3659.09 4867.42,3479.12 4944.42,3402.12 4944.42,3099.38 5107.42,2936.38 5107.42,2746 5165.42,2688 5213.42,2688 v4(5245.42,2720)
NetU26_20: U26.20 U29.14 | length 2695.6
  Top Layer w10: U26.20@6717.44,2302.14 6717.44,2269.06 6764.5,2222 7096.52,2222 7104.52,2230 7131.1,2230 7152.1,2251 7240,2251 7318.42,2329.42 7318.42,2933.18 7252.42,2999.18 7252.42,3188.72 7337.42,3273.72 7337.42,3666.75 7155.16,3849 6880,3849 6865.98,3863.02 U29.14@6821.05,3863.02
NetU26_21: U26.21 U29.13 | length 2602.3
  Top Layer w10: U26.21@6737.13,2302.14 6737.13,2274.83 6771.96,2240 7089.06,2240 7097.06,2248 7123.65,2248 7144.65,2269 7232.54,2269 7300.42,2336.87 7300.42,2925.72 7234.42,2991.72 7234.42,3196.18 7319.42,3281.18 7319.42,3659.29 7147.71,3831 6872.54,3831 6866.12,3837.43 U29.13@6821.05,3837.43
NetU26_22: U26.22 U29.12 | length 2509
  Top Layer w10: U26.22@6756.81,2302.14 6756.81,2280.6 6779.42,2258 7081.61,2258 7089.61,2266 7116.19,2266 7137.19,2287 7225.09,2287 7282.42,2344.33 7282.42,2918.27 7216.42,2984.27 7216.42,3203.63 7301.42,3288.63 7301.42,3651.83 7141.41,3811.84 U29.12@6821.05,3811.84
NMI: TP3.1 U14.89 | length 416.2
  Top Layer w10: TP3.1@1873,4576 1873,4518 1904,4487 1904,4291 v1(1890,4277)
  Bottom Layer w10: U14.89@1873.68,4185.15 1873.68,4260.69 v1(1890,4277)
NRS_AFE_: U2.39 U14.15 | length 8639.5
  Top Layer w10: U2.39@7274.55,1567.03 7321.94,1567.03 7334.96,1580.05 7517.95,1580.05 7537,1561 7637,1561 v1(7645,1553)
  MidLayer2 w10: v8(2606,3882) 2631.5,3856.5 2631.5,3555.5 2958,3229 2958,2394 2988.38,2363.62 2988.38,2266.47 2997.42,2257.43 2997.42,2232.54 2940.25,2175.37 2940.25,1866.62 2971.42,1835.46 2971.42,1805.46 2990.42,1786.46 v4(2990.42,1298)
  MidLayer3 w10: v4(2990.42,1298) 3021.42,1267 3060.42,1267 3074.42,1281 3568.43,1281 3584.43,1297 5415,1297 5742,1624 6275,1624 6414,1485 6577.34,1485 6597.58,1505.24 7277.66,1505.24 7353.42,1581 7534.44,1581 7562.44,1553 v1(7645,1553)
  Bottom Layer w10: U14.15@2157.15,3842.63 2200.28,3842.63 2225.64,3817.27 2368.25,3817.27 2369.98,3819 2418.54,3819 2529.54,3930 2578,3930 2606,3902 v8(2606,3882)
NRST: J7.15 U7.2 | length 4961.1
  Top Layer w7: v1(6907,4199) 6936,4170 7018.79,4170 7026.13,4177.35 U7.2@7026.13,4195.91
  Top Layer w10: v8(2884,4542) 2911,4569 J7.15@2911,4716
  MidLayer3 w10: v8(2884,4542) 2884,4619.37 2937.83,4673.2 3302.38,4673.2 3320.38,4655.2 3728.2,4655.2 3746.52,4673.52 3869.71,4673.52 3901.19,4705 4535.28,4705 4589.28,4651 4696.28,4651 4919.28,4428 5212.68,4428 5372.68,4588 5944.49,4588 5956.88,4600.38 6212.4,4600.38 6252.01,4640 6594.91,4640 6729.73,4505.19 6729.73,4356.39 6819.11,4267 6839,4267 v1(6907,4199)
NRST_: C22.1 R65.2 U8.3 U14.64 | length 838.2
  MidLayer2 w10: v7(1235,3892) 1235,3932.06 1302,3999.06 1302,4096.76 1274,4124.76 v7@1274,4216
  Bottom Layer w10: R65.2@1214.12,4151 1214.24,4151.13 U8.3@1214.24,4216.6 1272.4,4216.6 v7(1273,4216) ; v7(1235,3892) 1246,3903 1365.7,3903 1373.85,3911.15 ; C22.1@1373.85,3933.69 1373.85,3911.15 ; U14.64@1550.85,3901.69 1383.32,3901.69 1373.85,3911.15
NSD_AFE_: U2.40 U14.62 | length 9175.2
  Top Layer w10: U2.40@7274.55,1586.71 7316.17,1586.71 7327.51,1598.05 7525.4,1598.05 7544.46,1579 7637,1579 v1(7645,1587)
  MidLayer2 w10: v8(2606,3963) 2633,3936 2633,3880.46 2649.5,3863.96 2649.5,3565.5 3006.42,3208.58 3006.42,2273.88 3015.42,2264.88 3015.42,1786.91 3045.42,1756.91 v4(3045.42,1297)
  MidLayer3 w10: v7(1853.5,3914.5) 1860.5,3921.5 2187.5,3921.5 2229,3963 v8(2606,3963) ; v4@3045.42,1299 3560.98,1299 3576.98,1315 5407.54,1315 5734.54,1642 6282.46,1642 6421.46,1503 6569.88,1503 6590.12,1523.24 7270.2,1523.24 7345.96,1599 7541.9,1599 7553.9,1587 v1(7645,1587)
  Bottom Layer w10: U14.62@1550.85,3862.31 1610.38,3862.31 1649.06,3901 1840,3901 v7(1853.5,3914.5)
NSD_AFE_CHP_: J2.25 R50.2 R57.1 U2.38 U7.38 | length 4901.7
  Top Layer w7: v1(6829,4395) 6838.13,4385.87 U7.38@6977.91,4385.87
  Top Layer w10: J2.25@6448,4864 6448,4831.09 6543.09,4736 6672.71,4736 6821,4587.71 6821,4447.09 6829,4439.09 v1@6829,4405 ; U2.38@7274.55,1547.34 7328.66,1547.34 7343.37,1562.05 7364.5,1562.05 7388.55,1538 7416,1538 7427.42,1526.58 ; R50.2@7428.42,1452 7428.42,1499 R57.1@7427.42,1500 7427.42,1526.58 ; v7(7470,3787) 7447,3764 7447,3263 7483,3227 7483,3095.26 v8(7508,3070.26) ; v1(7645,1513) 7621,1537 7437.83,1537 7427.42,1526.58
  Bottom Layer w10: v1(6829,4395) 6853,4371 6853,3908.37 6995.37,3766 7449,3766 v7(7470,3787) ; v8(7508,3070.26) 7680,2898.26 7680,1548 v1(7645,1513)
P_IN_1: D22.2 PING_IN1.1 | length 676
  Top Layer w20: D22.2@6167.01,1033 6269.5,1033 6340,962.5 6340,662 6265.53,587.53 PING_IN1.1@6265.53,519.58
P_IN_2: D18.2 PING_IN1.2 | length 348.2
  Top Layer w20: D18.2@6167.58,863.06 6167.58,795.42 6178.91,784.09 PING_IN1.2@6178.91,519.58
P_IN_3: PING_IN1.3 R55.1 U15.5 | length 1286.5
  Top Layer w10: 6615,983 U15.5@6646.5,983
  Top Layer w20: 6615,983 6588,956 6588,858 v5(6621,825)
  MidLayer3 w20: PING_IN1.3@6092.3,519.58 6156.72,584 6460,584 6621,745 v5(6621,825)
  Bottom Layer w20: R55.1@5917,817 5917,773 6092.3,597.7 PING_IN1.3@6092.3,519.58
P_IN_4: PING_IN1.4 R51.1 U15.4 | length 1354.6
  Top Layer w10: 6604,1012 6618.53,1012 6627.53,1003 U15.4@6646.5,1003
  Top Layer w20: v3(6571,825) 6560,836 6560,968 6604,1012
  MidLayer3 w20: PING_IN1.4@6005.68,519.58 6016.73,519.58 6109.15,612 6448.4,612 6571,734.6 v3(6571,825)
  Bottom Layer w20: R51.1@5869.53,817.02 5869.53,775.47 6005.68,639.32 PING_IN1.4@6005.68,519.58
P_OUT_5: PING_OUT1.5 R45.2 U15.1 | length 1250.4
  Top Layer w10: 6703,941 6703.5,941.5 U15.1@6703.5,963
  Top Layer w20: 6703,941 6703,903.46 v1(6779.73,826.73) 6918.9,687.57 6918.9,553.33 PING_OUT1.5@6865.46,499.9
  MidLayer1 w20: v1(6766,1287) 6689.5,1210.5 6689.5,1097.42 6779.73,1007.19 v1(6779.73,826.73)
  Bottom Layer w10: v1(6766,1287) 6766,1301.98 6828.75,1364.73 6840,1364.73 6849.44,1374.17 R45.2@6849.44,1392
P_OUT_6: PING_OUT1.6 R43.2 U15.3 | length 1518.9
  Top Layer w10: U15.3@6703.5,1003 6756.06,1003 6784,975.06
  Top Layer w20: PING_OUT1.6@6778.85,499.9 6832.28,446.46 6887.6,446.46 6946.9,505.76 6946.9,709.57 v1(6829.73,826.73) 6784,872.46 6784,975.06
  MidLayer1 w20: v1(6635,1256) 6635,860 6635.5,860 6711.5,784 6787,784 v1(6829.73,826.73)
  Bottom Layer w20: v1(6635,1256) R43.2@6670.44,1256
P_OUT_7: PING_OUT1.7 R42.2 U15.6 | length 1576.5
  Top Layer w10: 6646,944 6646,962.5 U15.6@6646.5,963
  Top Layer w20: 6646,944 6658,932 v5(6658,773) 6552.19,667.19 6552.19,595.88 6583,565.06 6583,562 6672,562 6692.24,541.76 PING_OUT1.7@6692.24,499.9
  MidLayer2 w20: v3(6550,1551) 6550,1470.91 6576.42,1444.5 6576.42,919.08 6658,837.5 v5(6658,773)
  Bottom Layer w20: v3(6550,1551) 6578,1523 R42.2@6669.88,1523
P_OUT_DOUT_LS: PING_OUT1.3 R262.2 | length 565.3
  Bottom Layer w20: R262.2@6612,907 6566,907 6536,877 6536,592 6566,562 6636.23,562 PING_OUT1.3@6692.24,618.01
P_OUT_PING_IO_LS: PING_OUT1.4 R259.2 | length 360.8
  Bottom Layer w20: PING_OUT1.4@6605.62,618.01 6605.62,667.62 6708,770 R259.2@6708,936.44
PB2: J1.6 J4.34 U14.72 | length 3688.6
  Top Layer w10: J4.34@1333,5028 1333,5074 v8(1363,5104)
  MidLayer2 w10: v8(1363,5104) 1363,5021 1401,4983 1401,4264 v7(1606,4059)
  Bottom Layer w10: v8(1363,5104) 1363,5154 1393,5184 3289,5184 3353,5120 3353,5016 J1.6@3506,4863 ; U14.72@1550.85,4059.17 1605.83,4059.17 v7(1606,4059)
PB3: J1.5 J4.36 U14.65 | length 4016.4
  Top Layer w10: J4.36@1358,5028 1358,5059 v8(1403,5104)
  MidLayer2 w10: v8(1403,5104) 1403,5006.46 1419,4990.46 1419,4282.06 1634,4067.06 v7(1634,3922)
  Bottom Layer w10: v8(1403,5104) 1403,5136 1433,5166 3281.54,5166 3335,5112.54 3335,4860 3380,4815 3558,4815 J1.5@3606,4863 ; U14.65@1550.85,3921.37 1633.37,3921.37 v7(1634,3922)
PING_IO_LS: D55.1 Q52.2 R161.2 R261.1 | length 260.3
  Bottom Layer w20: R261.1@6529,1150.56 6597.56,1150.56 Q52.2@6598,1151 6598,1163 6579.42,1181.58 R161.2@6579.42,1207 6579.42,1241.42 6602.42,1264.42 D55.1@6602.42,1324.88
PING_LS_IN: R43.1 R46.1 U18.47 | length 568.9
  Bottom Layer w10: R43.1@6735.56,1254 6847.43,1254 6863.43,1270 6864.64,1270 6864.68,1270.04 6905,1270.04 ; R46.1@6905,1335 6905,1270.04 ; U18.47@7052.11,1502.07 7052.11,1458.78 7042.92,1449.59 7042.92,1348.37 6964.59,1270.04 6905,1270.04
PING_LS_OUT: R45.1 U18.48 | length 195.4
  Bottom Layer w10: R45.1@6904.56,1392 6959.87,1392 7032.43,1464.55 U18.48@7032.43,1502.07
PWM_CLP_BOT: R48.1 U24.2 U27.18 | length 809.7
  Top Layer w10: v5(4428.42,3792) 4429.42,3792 4441.32,3780.1 U27.18@4493.28,3780.1
  MidLayer2 w20: v5(4376.42,4181) 4475.42,4082 4475.42,3839 v5(4428.42,3792)
  Bottom Layer w20: U24.2@4310.82,3853.51 4310.82,3823.9 4325.72,3809 4411.42,3809 v5(4428.42,3792) ; v5@4376.42,4178 v5(4376.42,4181) 4376.53,4181.12 R48.1@4376.53,4306 R48.1@4376.53,4308
PWM_CLP_TOP: R49.1 U28.2 U29.18 | length 966.7
  Top Layer w10: v5(6527.84,3798.15) 6528.84,3798.15 6540.74,3786.25 U29.18@6592.7,3786.25
  MidLayer2 w20: v5(6446,4082) 6507.42,4082 6573.42,4016 6573.42,3843.72 v5(6527.84,3798.15)
  Bottom Layer w20: U28.2@6353.42,3861 6353.42,3828 6364.42,3817 6411.64,3817 6422.6,3827.95 6498.03,3827.95 v5(6527.84,3798.15) ; R49.1@6391.53,4321 R49.1@6391.53,4317 6391.53,4110.88 6420.42,4082 v5(6446,4082)
RED: D48.2 U14.95 | length 1429.3
  Top Layer w10: v11(876,4148) D48.2@876,4215
  MidLayer3 w10: v11(876,4148) 928.54,4148 1040.54,4260 1497,4260 1535,4298 1645,4298 1797,4146 1824,4146 1839,4131 1839,4098.52 1858.52,4079 1938,4079 v7(1967,4108)
  Bottom Layer w10: v7(1967,4108) 1991.8,4132.8 U14.95@1991.8,4185.15
RGND: C3.2 C5.2 C228.2 C250.1 C251.2 NT4.1 R125.2 U1.2 U2.31 U3.4 U41.4 | length 5059.2
  Top Layer w10: v1(6999.42,1128) 7001,1126.42 v1(7001,1097) 7018,1080 7046.42,1080 7058.52,1092.1 U3.4@7058.52,1133.84 ; v1(7140.42,1405) 7140.42,1426 7147.92,1433.5 7147.92,1476.47 7150.54,1479.09 U2.31@7150.54,1502.07
  Top Layer w20: C251.2@6959.86,1213.44 C5.2@6959.86,1261.44 6959.86,1335.56 v3(6954.42,1341) v3(6994.42,1381) ; v1(7140.42,1405) v1(7165.42,1380) ; C3.2@7275.19,1096 C3.2@7280.19,1096 7355.42,1096 7363.92,1104.5 v5(7368.42,1100) v5(7408.42,1100) R125.2@7448.42,1100 ; C228.2@7280.19,1047 7280.19,1094.5 C3.2@7280.69,1095 ; U41.4@7360.41,614.14 7391,614
  Top Layer w25: 7391,614 v5@7425.41,614.14 ; v5(7425.42,613) v5@7425.42,614.14 ; v5(7425.42,664.18) v5@7425.42,614.14 ; v5@7425.42,665.18 C250.1@7425.42,710 7498.42,710 7517.42,729 U1.2@7517.42,757.76
  MidLayer4 w20: v1(7140.42,1405) v1(7165.42,1380) ; v5@7363.92,1104.5 v5(7368.42,1100)
  MidLayer4 w30: v1(7001,1097) 7001,1126.42 v1(6999.42,1128) 6999.42,1148 7073.42,1222
  MidLayer4 w50: NT4.1@5500,634.96 5500,285 5615,170 7172,170 7384,382 7384,571.58 v5(7425.42,613) v5(7425.42,664.18) 7425.42,709.58 7408.42,726.58 v5(7408.42,1100) v5(7368.42,1100) 7367.42,1099 7196.42,1099 7073.42,1222 v3(6954.42,1341) v3(6994.42,1381) 7116.42,1381 v1(7140.42,1405)
RGND_BSP: C74.2 C75.2 C77.2 C78.2 C79.2 NT6.1 R128.1 R132.1 R135.1 R139.1 U18.31 | length 5508.9
  MidLayer1 w25: v3(7607.42,1905) 7660.42,1905
  MidLayer1 w50: NT6.1@5505,502 5505,280 5610,175 7180,175 7700,695 7700,1668 7688,1680 v3(7641.42,1680) v3(7641.42,1720) ; v3@7485.13,2326 7543.42,2326 7660.42,2209 7660.42,1905 7660.42,1749 v3@7641.42,1730
  Bottom Layer w10: U18.31@7274.55,1626.08 7380.9,1626.08 7391.82,1637 7473.42,1637 7486.98,1650.56 C75.2@7486.98,1671 C75.2@7486.98,1676
  Bottom Layer w20: R128.1@7384.42,2172 C78.2@7384.42,2220 7384.42,2267.42 C79.2@7384.07,2267.77 7384.07,2323.65 7386.42,2326 7425.42,2326 7429.42,2322 7433.42,2326 ; v3(7641.42,1680) v3(7641.42,1720)
  Bottom Layer w25: 7433.42,2326 v3(7483.42,2326) ; C75.2@7486.98,1676 7486.98,1707.56 7559.42,1780 C74.2@7559.42,1805.88 ; R132.1@7512.42,1805.88 C74.2@7559.42,1805.88 ; C77.2@7512.42,1906 R135.1@7560.42,1906 ; C74.2@7559.42,1806 C74.2@7559.42,1805.88 ; R135.1@7560.42,1905 v3(7607.42,1905) ; v3@7641.42,1730 7641.42,1788 7623.53,1805.88 C74.2@7560.42,1805.88 C74.2@7559.42,1805.88
RS_EMB1428_: R282.2 U6.35 U14.12 U26.35 | length 9005.2
  Top Layer w10: U6.35@5152.77,2964.83 5168.21,2964.83 5179.42,2976.04 5179.42,2992.42 5226.42,3039.42 v8@5226.42,3109 ; U26.35@6821.77,2524.58 6837.21,2524.58 6846.59,2533.96 6846.59,2590.59 6875,2619 v1(6875,3019)
  MidLayer2 w10: v5(4971.42,3941) 4970.42,3940 5060,3850.42 5060,3267.24 v8@5219.33,3107.91
  MidLayer3 w10: v1(2062,3851) 2080.54,3851 2086.54,3845 2581.48,3845 2590.48,3836 2656.54,3836 2695.54,3797 4125.08,3797 4253.08,3925 4662.99,3925 4708.99,3971 4941.42,3971 v5(4971.42,3941) ; v8(5220.42,3109) 5246.31,3083.1 5246.31,3007.68 5265.99,2988 5312,2988 5581,3257 6256,3257 6306,3207 6714.3,3207 6875,3046.3 v1(6875,3019)
  Bottom Layer w10: v1@2062,3856 2062,3888 2075.68,3901.69 U14.12@2157.15,3901.69 ; R282.2@6385,4735.88 6385,4713 6435,4663 6672.63,4663 6749,4586.63 6749,4193.09 6697,4141.09 6697,4010.46 6752,3955.46 6752,3917.54 6786.63,3882.91 6827.54,3882.91 7006.92,3703.54 7006.92,3337.92 6875,3206 v1(6875,3019)
SCLK_1_: C61.2 J2.31 R157.2 U6.27 U7.32 U14.28 U26.27 U31.16 U44.6 | length 18182.3
  Top Layer w7: U7.32@7073.38,4434.09 7073.38,4471.62 7069,4476 v1(7069,4491) ; v1@7073.38,4491.38 7073,4491 v1(7069,4491) ; 7078,4622 7078,4500 v1(7069,4491)
  Top Layer w10: U6.27@5152.77,2807.35 5271.76,2807.35 5274.42,2810 5296.85,2810 5346.92,2860.07 5346.92,3071.92 5356,3081 v5(5356,3131) ; v1(6524,4911) 6524,4865 J2.31@6523,4864 6523,4833 6566,4790 6910,4790 7078,4622 ; U26.27@6821.77,2367.1 6921.86,2367.1 6932.96,2356 7078.91,2356 7111.91,2389 v3(7130.42,2389)
  MidLayer2 w10: v8(2385,1295) 2424.5,1334.5 2424.5,1749.54 2513.42,1838.46 v3(2513.42,1862) 2513.42,1910.09 2436,1987.5 2436,2248.26 2517.78,2330.04 2517.78,2562.22 2432,2648 v11(2432,2973) ; v7(5107,4522) 5107,4477.36 5228.42,4355.95 5228.42,3258.58 v5(5356,3131) ; v7(7099.42,2991) 7177.42,2913 7177.42,2436 v3(7130.42,2389) 7130.42,2232.34 7219.5,2143.26 7219.5,1825.53 7225,1820.03 7225,1566 7114,1455 7114,897 7122,889 v1(7143.08,889)
  MidLayer3 w10: v8(2385,1295) 2415,1265 2415,905 2509,811 5755.12,811 5805.12,761 5844.88,761 5894.88,811 6514.57,811 6558.57,855 6633.43,855 6661.43,827 6743.4,827 6769.4,801 6869.16,801 6880.35,812.18 7066.26,812.18 v1(7143.08,889) ; v3(2513.42,1862) v3@2519.99,1862 ; v7(5107,4522) 5119.54,4522 5139.54,4502 5181.38,4502 5339.38,4660 5914.67,4660 5927.05,4672.38 6182.57,4672.38 6222.19,4712 6624.73,4712 6801.73,4535.01 6801.73,4386.21 6818.44,4369.5 6952.36,4369.5 7019.86,4437 7055,4437 7069,4451 v1(7069,4491) ; v5(5356,3131) 5536,3311 6755,3311 7021,3045 7068.42,3045 7099.42,3014 v7(7099.42,2991)
  Bottom Layer w10: U14.28@2050.85,3578.85 2050.85,3535.24 2128.59,3457.5 2309.5,3457.5 2381.5,3385.5 2381.5,3246.5 2329,3194 ; U44.6@2281.52,3194 2329,3194 ; v11(2432,2973) 2390.5,3014.5 2390.5,3132.5 2329,3194 ; U31.16@2453.71,1824.57 2495.98,1824.57 2513.42,1842 v3(2513.42,1862) ; v1(6524,4911) 6541.76,4893.24 C61.2@6541.76,4861 ; v1(7143.08,889) 7153.08,899 7232,899 7240.31,907.31 R157.2@7240.31,934.79
SCLK_2_: C51.1 J1.4 J4.22 J5.5 U7.3 U14.60 | length 10848.8
  Top Layer w7: v1(6966,4145) 7015,4145 7041.88,4171.88 U7.3@7041.88,4195.91
  Top Layer w10: J4.22@1183,5028 1183,5060 1187,5064 1187,5140 1183,5144 v8(1183,5188)
  MidLayer2 w10: v7(798,3461.86) 747.5,3512.36 747.5,4170.5 810,4233 810,4830.48 769.5,4870.98 769.5,5051.96 905.54,5188 v8(1183,5188) ; v1(6966,4145) 7026,4205 7026,4507 7079,4560 7079,4621 7068,4632 v1(7068,4813)
  MidLayer3 w10: v8(1183,5188) 1246,5188 1280,5154 1280,5110.94 1312.51,5078.42 1413.8,5078.42 1554.38,5219 3265.91,5219 3354,5130.91 3354,4850.68 3387.49,4817.2 3660.2,4817.2 J1.4@3706,4863 3791,4948 4062.91,4948 4092.91,4918 5143.18,4918 5160.18,4935 5518.88,4935 5649.88,4804 5855.02,4804 5941.02,4890 6082.06,4890 6116.06,4856 6684.38,4856 6729.88,4810.5 6868.03,4810.5 6883.53,4826 7055,4826 v1(7068,4813)
  Bottom Layer w10: J5.5@741.56,3415.24 780.24,3415.24 798,3433 v7(798,3461.86) 882.86,3461.86 938,3517 938,3691 1091.5,3844.5 1249.02,3844.5 1268.52,3864 1477,3864 1518.06,3822.94 U14.60@1550.85,3822.94 ; v1(6966,4145) 6967,4144 C51.1@7013.44,4144
SCLK_ADC_: R157.1 R158.1 U2.43 U3.8 | length 1906.7
  Top Layer w10: U3.8@7077.92,972.13 U3.8@7078.21,972.42 7078.21,1005.21 7094,1021 7133,1021 7143.08,1010.92 v1(7143.08,960) ; U2.43@7274.55,1645.77 7297.73,1645.77 7338.12,1686.15 7389.97,1686.15 7423.13,1653 7575.99,1653 7578.99,1650 7665,1650 7678,1637 7678,1014 v11(7645,981)
  MidLayer3 w10: v1(7143.08,960) 7469,960 7489,940 7604,940 v11(7645,981)
  Bottom Layer w10: v1(7143.08,960) 7172.42,989.35 R158.1@7192.31,989.35 7192.87,989.91 R157.1@7240.31,989.91
SCLK_FPGA_: R80.2 R158.2 | length 3338.6
  Top Layer w10: v1(7326,3903.31) R80.2@7326,3932.82 R80.2@7326,3936.76
  MidLayer2 w10: v1(7143.08,923) 7181,923 7267,1009 7267,1161.43 7243.5,1184.93 7243.5,1826.98 7237.5,1832.98 7237.5,2170.96 7228,2180.46 7228,2981.53 7247,3000.53 7247,3334.53 7260,3347.53 7260,3537.57 7378.5,3656.07 7378.5,3837.16 7406.5,3865.16 7406.5,3913.5 7391.56,3928.44 7370.44,3928.44 7345.32,3903.31 v1(7326,3903.31)
  Bottom Layer w10: v1(7143.08,923) 7154.3,934.23 R158.2@7192.31,934.23
SDO_ADC_: R155.1 R156.1 U2.44 U3.7 | length 2368.9
  Top Layer w10: v1(7023,784) R155.1@7023,846 R155.1@7023,852 ; R155.1@7025,854 R155.1@7023,852 ; U3.7@7058.92,972.02 U3.7@7058.52,972.42 7058.5,937.5 7049,928 7036,928 7023,915 R156.1@7023,894 R155.1@7023,852 ; U2.44@7274.55,1665.45 7291.87,1665.45 7335.36,1708.95 7335.36,1734.47 7383.39,1782.5 7421.57,1782.5 7522.42,1883.35 7522.42,2074 v7(7520.42,2076)
  MidLayer2 w10: v1(7023,784) 7052,813 7240,813 7303,876 7303,1759 7520.42,1976.42 v7(7520.42,2076)
SP7: J2.23 R87.1 U7.39 | length 1109
  Top Layer w7: 6803,4383 6815.88,4370.12 U7.39@6977.91,4370.12
  Top Layer w10: v1(6434,4911) 6423,4900 J2.23@6423,4864 6423,4830.63 6535.63,4718 6665.26,4718 6803,4580.26 6803,4383
  Bottom Layer w10: v1(6434,4911) 6462,4883 6468,4883 6529,4822 R87.1@6529,4791
SP8: J2.21 R285.1 U7.40 | length 1225.6
  Top Layer w7: 6785,4377 6807.63,4354.37 U7.40@6977.91,4354.37
  Top Layer w10: v1(6424,4951) 6401.5,4928.5 6401.5,4867.5 J2.21@6398,4864 6398,4830.18 6528.18,4700 6657.8,4700 6785,4572.8 6785,4377
  Bottom Layer w10: 6401.47,4897.47 6413.44,4885.5 6413.5,4885.5 6481,4818 R285.1@6481,4791 ; 6401.5,4897.5 6401.5,4928.5 v1(6424,4951)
